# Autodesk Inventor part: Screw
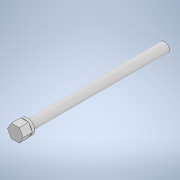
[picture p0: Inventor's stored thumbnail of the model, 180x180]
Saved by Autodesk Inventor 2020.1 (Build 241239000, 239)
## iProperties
Created: 2019-12
Part Number: Screw
Material: Generic
Document SubType Name: Modeling
Designer: Patrick Everitt
Density: 1 g/cm^3
Appearance: Default
Author: Patrick Everitt
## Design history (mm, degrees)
sketch "Sketch1"
  geometry: C1 r 14.287 at (0, 0); 1 further point
  constraints: 1 centre point, 1 coincident
  dimensions: "d0" = 28.575 diameter of C1
extrude "Extrusion1" new body sketch "Sketch1" distance "d1" = 457.2; taper "d2" = 0 deg
sketch "Sketch2"
  geometry: L1 (-11.915, 20.638)-(11.915, 20.638); L2 (11.915, 20.638)-(23.83, 0); L3 (23.83, 0)-(11.915, -20.637); L4 (11.915, -20.637)-(-11.915, -20.637); L5 (-11.915, -20.637)-(-23.83, 0); L6 (-23.83, 0)-(-11.915, 20.638); 2 further points
  constraints: 12 end point, 1 coincident, 1 horizontal, 13 other
  dimensions: "d3" = 20.6375 distance from line of L2 point (0, 0)
extrude "Extrusion2" join sketch "Sketch2" distance "d4" = 28.575; taper "d5" = 0 deg
sketch "Sketch3"
  geometry: C1 r 14.287 at (0, 0) reference; C2 r 22.225 at (0, 0); 1 further point
  constraints: 1 centre point, 1 coincident
  dimensions: "d6" = 44.45 diameter of C2
extrude "Extrusion3" join sketch "Sketch3" distance "d7" = 8.3312; taper "d8" = 0 deg
sketch "Sketch4"
  geometry: 2 further points
  constraints: 1 coincident
hole "Hole1" sketch "Sketch4" at (0, 0) diameter "d9" = 6.4008; stored, may be unused: countersink angle "d13" = 82 deg, drill point angle "d15" = 118 deg; dims "d10" = 15.875, "d11" = 9.525, "d12" = 6.35, "d14" = 22.9362
body "Solid1"
